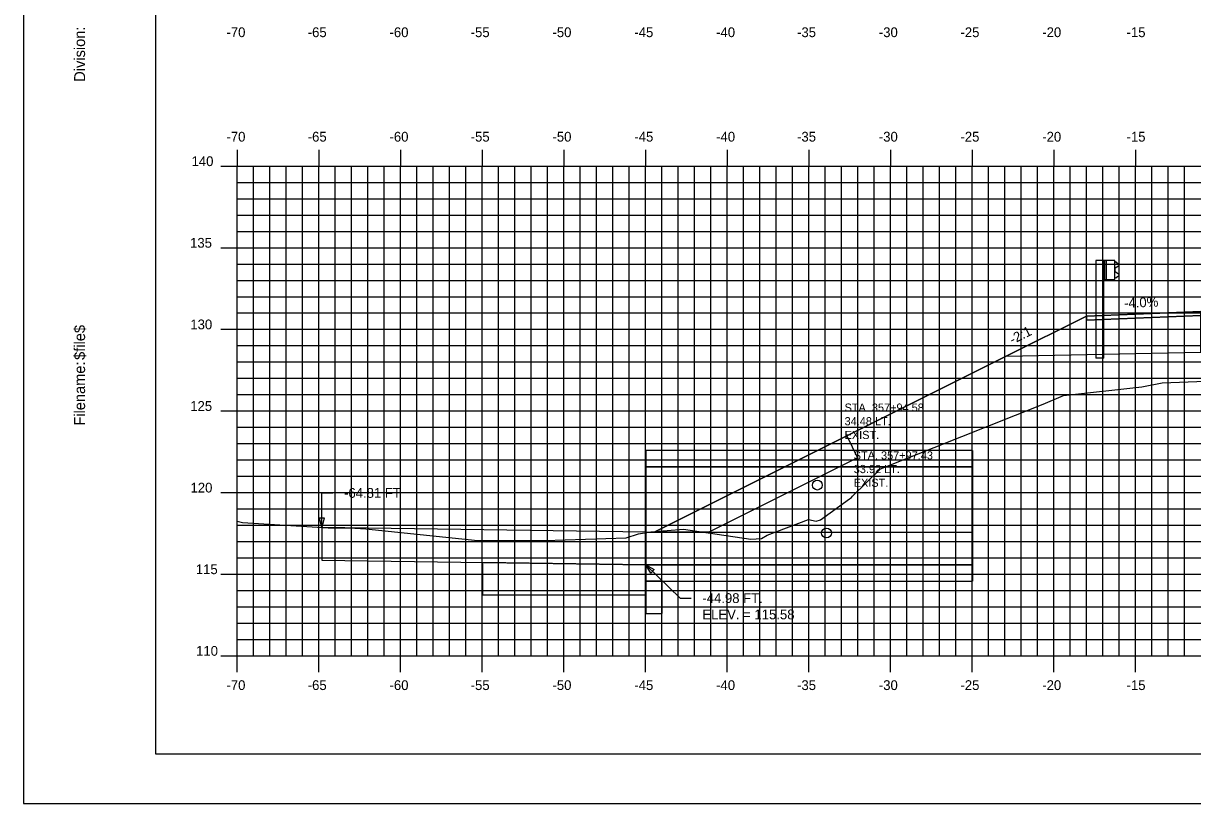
# Model space of a CAD drawing. Extents: x 1146081 to 1146251, y 608981 to 609091.
# Drawn here: x 1146081.1 to 1146152.7, y 608981.3 to 609029.1 of the extents above; entities that cross this region are included whole.
import ezdxf

# ---------------------------------------------------------------- set-up
doc = ezdxf.new("R2010")
doc.units = 0
for name, color, linetype in [('ANNOTATION', 7, 'Continuous'), ('BORDER', 7, 'Continuous'), ('D_Drainage_Culvert', 7, 'Continuous'), ('D_Guardrail_Beam_Lt', 7, 'Continuous'), ('D_Roadway_Edge_Shoulder', 7, 'Continuous'), ('D_Roadway_SlopeLines', 7, 'Continuous'), ('D_Roadway_SubGrade', 7, 'Continuous'), ('D_Text_Monospaced', 7, 'Continuous'), ('D_Text_Standard', 7, 'Continuous'), ('H_V ANNOTATION', 7, 'Continuous'), ('MAJOR', 7, 'Continuous'), ('MINOR', 7, 'Continuous'), ('PATTERNING', 7, 'Continuous'), ('PLOT BOUNDARY', 7, 'Continuous'), ('S_Drainage_Invert', 7, 'Continuous'), ('S_Roadway_Centerline', 7, 'Continuous')]:
    doc.layers.add(name, color=color, linetype=linetype)

msp = doc.modelspace()

# ---------------------------------------------------------------- linework, layer by layer
msp.add_lwpolyline([(1146119.749, 608997.946), (1146139.24, 609007.691), (1146141.24, 609008.691), (1146146.157, 609011.15), (1146146.158, 609011.15), (1146153.158, 609011.43), (1146164.158, 609011.65), (1146175.158, 609011.43), (1146182.158, 609011.15), (1146187.075, 609008.692), (1146189.075, 609007.692), (1146204.079, 609000.19)])
at = {"layer": 'ANNOTATION'}
msp.add_line((1146139.178, 609002.915), (1146139.178, 608994.915), dxfattribs=at)
at = {"layer": 'BORDER'}
msp.add_lwpolyline([(1146089.158, 608984.335), (1146249.158, 608984.335), (1146249.158, 609089.335), (1146089.158, 609089.335)], close=True, dxfattribs=at)
at = {"layer": 'D_Drainage_Culvert'}
for points in [[(1146139.178, 608994.915), (1146139.178, 609002.915), (1146119.178, 609002.915), (1146119.178, 608994.915)], [(1146139.178, 608995.915), (1146139.178, 609001.915), (1146119.178, 609001.915), (1146119.178, 608995.915)], [(1146119.178, 608994.915), (1146119.181, 608992.915), (1146120.181, 608992.916), (1146120.178, 608994.916)]]:
    msp.add_lwpolyline(points, close=True, dxfattribs=at)
at = {"layer": 'D_Guardrail_Beam_Lt'}
for p, q in [((1146146.729, 609014.56), (1146146.729, 609008.56)), ((1146147.2, 609014.56), (1146146.729, 609014.56)), ((1146147.887, 609014.56), (1146147.2, 609014.56)), ((1146147.2, 609014.56), (1146147.2, 609013.394)), ((1146147.262, 609014.56), (1146147.262, 609013.394)), ((1146147.366, 609014.56), (1146147.366, 609013.394)), ((1146147.887, 609013.394), (1146147.887, 609014.56)), ((1146147.887, 609014.477), (1146147.961, 609014.462)), ((1146147.977, 609014.456), (1146148.12, 609014.356)), ((1146147.891, 609014.012), (1146147.891, 609013.942)), ((1146148.12, 609014.213), (1146147.925, 609014.076)), ((1146147.925, 609013.877), (1146148.12, 609013.741)), ((1146148.12, 609013.598), (1146147.977, 609013.498)), ((1146147.2, 609013.394), (1146147.887, 609013.394)), ((1146147.22, 609008.56), (1146147.22, 609013.394)), ((1146147.961, 609013.491), (1146147.887, 609013.477)), ((1146147.22, 609008.56), (1146146.729, 609008.56))]:
    msp.add_line(p, q, dxfattribs=at)
for centre, major_axis, start_param, end_param in [((1146147.953, 609014.422), (0.0417, 0), 0.959931, 1.376053), ((1146148.07, 609014.284), (0.0877, 0), 5.323254, 7.243116), ((1146147.97, 609014.012), (-0.0789, 0), 5.323254, 6.283185), ((1146147.97, 609013.942), (-0.0789, 0), 6.283185, 7.243116), ((1146148.07, 609013.67), (0.0877, 0), 5.323254, 7.243116), ((1146147.953, 609013.532), (0.0417, 0), 4.907132, 5.323254)]:
    msp.add_ellipse(centre, major_axis=major_axis, ratio=0.995501, start_param=start_param, end_param=end_param, dxfattribs=at)
at = {"layer": 'D_Roadway_Edge_Shoulder'}
msp.add_lwpolyline([(1146153.158, 609011.43), (1146146.158, 609011.15), (1146146.158, 609010.9), (1146153.158, 609011.18)], close=True, dxfattribs=at)
at = {"layer": 'D_Roadway_SlopeLines'}
for points in [[(1146141.24, 609008.691), (1146139.24, 609007.691)], [(1146139.24, 609007.691), (1146119.688, 608997.915)]]:
    msp.add_lwpolyline(points, dxfattribs=at)
at = {"layer": 'D_Roadway_SubGrade'}
msp.add_lwpolyline([(1146153.158, 609011.013), (1146153.158, 609011.18), (1146146.158, 609010.9), (1146146.158, 609011.15), (1146146.157, 609011.15), (1146141.24, 609008.691), (1146153.158, 609008.93)], close=True, dxfattribs=at)
at = {"layer": 'D_Text_Standard'}
for points in [[(1146099.348, 608998.2), (1146099.34, 609000.312), (1146100.02, 609000.312)], [(1146119.178, 608995.915), (1146121.28, 608993.866), (1146121.96, 608993.866)]]:
    msp.add_lwpolyline(points, dxfattribs=at)
for points in [[(1146099.348, 608998.2), (1146099.2, 608998.782), (1146099.492, 608998.783)], [(1146119.178, 608995.915), (1146119.697, 608995.613), (1146119.493, 608995.405)]]:
    msp.add_lwpolyline(points, close=True, dxfattribs=at)
at = {"layer": 'MAJOR'}
for p, q in [((1146094.158, 609021.337), (1146094.158, 609020.335)), ((1146099.158, 609021.337), (1146099.158, 609020.335)), ((1146104.158, 609021.337), (1146104.158, 609020.335)), ((1146109.158, 609021.337), (1146109.158, 609020.335)), ((1146114.158, 609021.337), (1146114.158, 609020.335)), ((1146119.158, 609021.337), (1146119.158, 609020.335)), ((1146124.158, 609021.337), (1146124.158, 609020.335)), ((1146129.158, 609021.337), (1146129.158, 609020.335)), ((1146134.158, 609021.337), (1146134.158, 609020.335)), ((1146139.158, 609021.337), (1146139.158, 609020.335)), ((1146144.158, 609021.337), (1146144.158, 609020.335)), ((1146149.158, 609021.337), (1146149.158, 609020.335)), ((1146093.156, 609020.335), (1146094.158, 609020.335)), ((1146094.158, 609020.335), (1146234.158, 609020.335)), ((1146094.158, 608990.335), (1146094.158, 609020.335)), ((1146094.158, 608990.335), (1146094.158, 609020.335)), ((1146094.158, 609020.335), (1146234.158, 609020.335)), ((1146099.158, 608990.335), (1146099.158, 609020.335)), ((1146104.158, 608990.335), (1146104.158, 609020.335)), ((1146109.158, 608990.335), (1146109.158, 609020.335)), ((1146114.158, 608990.335), (1146114.158, 609020.335)), ((1146119.158, 608990.335), (1146119.158, 609020.335)), ((1146124.158, 608990.335), (1146124.158, 609020.335)), ((1146129.158, 608990.335), (1146129.158, 609020.335)), ((1146134.158, 608990.335), (1146134.158, 609020.335)), ((1146139.158, 608990.335), (1146139.158, 609020.335)), ((1146144.158, 608990.335), (1146144.158, 609020.335)), ((1146149.158, 608990.335), (1146149.158, 609020.335)), ((1146093.156, 609015.335), (1146094.158, 609015.335)), ((1146094.158, 609015.335), (1146234.158, 609015.335)), ((1146093.156, 609010.335), (1146094.158, 609010.335)), ((1146094.158, 609010.335), (1146234.158, 609010.335)), ((1146093.156, 609005.335), (1146094.158, 609005.335)), ((1146094.158, 609005.335), (1146234.158, 609005.335)), ((1146093.156, 609000.335), (1146094.158, 609000.335)), ((1146094.158, 609000.335), (1146234.158, 609000.335)), ((1146093.156, 608995.335), (1146094.158, 608995.335)), ((1146094.158, 608995.335), (1146234.158, 608995.335)), ((1146093.156, 608990.335), (1146094.158, 608990.335)), ((1146094.158, 608990.335), (1146234.158, 608990.335)), ((1146094.158, 608990.335), (1146234.158, 608990.335)), ((1146094.158, 608989.333), (1146094.158, 608990.335)), ((1146099.158, 608989.333), (1146099.158, 608990.335)), ((1146104.158, 608989.333), (1146104.158, 608990.335)), ((1146109.158, 608989.333), (1146109.158, 608990.335)), ((1146114.158, 608989.333), (1146114.158, 608990.335)), ((1146119.158, 608989.333), (1146119.158, 608990.335)), ((1146124.158, 608989.333), (1146124.158, 608990.335)), ((1146129.158, 608989.333), (1146129.158, 608990.335)), ((1146134.158, 608989.333), (1146134.158, 608990.335)), ((1146139.158, 608989.333), (1146139.158, 608990.335)), ((1146144.158, 608989.333), (1146144.158, 608990.335)), ((1146149.158, 608989.333), (1146149.158, 608990.335))]:
    msp.add_line(p, q, dxfattribs=at)
at = {"layer": 'MINOR'}
for p, q in [((1146095.158, 608990.335), (1146095.158, 609020.335)), ((1146096.158, 608990.335), (1146096.158, 609020.335)), ((1146097.158, 608990.335), (1146097.158, 609020.335)), ((1146098.158, 608990.335), (1146098.158, 609020.335)), ((1146100.158, 608990.335), (1146100.158, 609020.335)), ((1146101.158, 608990.335), (1146101.158, 609020.335)), ((1146102.158, 608990.335), (1146102.158, 609020.335)), ((1146103.158, 608990.335), (1146103.158, 609020.335)), ((1146105.158, 608990.335), (1146105.158, 609020.335)), ((1146106.158, 608990.335), (1146106.158, 609020.335)), ((1146107.158, 608990.335), (1146107.158, 609020.335)), ((1146108.158, 608990.335), (1146108.158, 609020.335)), ((1146110.158, 608990.335), (1146110.158, 609020.335)), ((1146111.158, 608990.335), (1146111.158, 609020.335)), ((1146112.158, 608990.335), (1146112.158, 609020.335)), ((1146113.158, 608990.335), (1146113.158, 609020.335)), ((1146115.158, 608990.335), (1146115.158, 609020.335)), ((1146116.158, 608990.335), (1146116.158, 609020.335)), ((1146117.158, 608990.335), (1146117.158, 609020.335)), ((1146118.158, 608990.335), (1146118.158, 609020.335)), ((1146120.158, 608990.335), (1146120.158, 609020.335)), ((1146121.158, 608990.335), (1146121.158, 609020.335)), ((1146122.158, 608990.335), (1146122.158, 609020.335)), ((1146123.158, 608990.335), (1146123.158, 609020.335)), ((1146125.158, 608990.335), (1146125.158, 609020.335)), ((1146126.158, 608990.335), (1146126.158, 609020.335)), ((1146127.158, 608990.335), (1146127.158, 609020.335)), ((1146128.158, 608990.335), (1146128.158, 609020.335)), ((1146130.158, 608990.335), (1146130.158, 609020.335)), ((1146131.158, 608990.335), (1146131.158, 609020.335)), ((1146132.158, 608990.335), (1146132.158, 609020.335)), ((1146133.158, 608990.335), (1146133.158, 609020.335)), ((1146135.158, 608990.335), (1146135.158, 609020.335)), ((1146136.158, 608990.335), (1146136.158, 609020.335)), ((1146137.158, 608990.335), (1146137.158, 609020.335)), ((1146138.158, 608990.335), (1146138.158, 609020.335)), ((1146140.158, 608990.335), (1146140.158, 609020.335)), ((1146141.158, 608990.335), (1146141.158, 609020.335)), ((1146142.158, 608990.335), (1146142.158, 609020.335)), ((1146143.158, 608990.335), (1146143.158, 609020.335)), ((1146145.158, 608990.335), (1146145.158, 609020.335)), ((1146146.158, 608990.335), (1146146.158, 609020.335)), ((1146147.158, 608990.335), (1146147.158, 609020.335)), ((1146148.158, 608990.335), (1146148.158, 609020.335)), ((1146150.158, 608990.335), (1146150.158, 609020.335)), ((1146151.158, 608990.335), (1146151.158, 609020.335)), ((1146152.158, 608990.335), (1146152.158, 609020.335)), ((1146094.158, 609019.335), (1146234.158, 609019.335)), ((1146094.158, 609019.335), (1146095.16, 609019.335)), ((1146094.158, 609018.335), (1146234.158, 609018.335)), ((1146094.158, 609018.335), (1146095.16, 609018.335)), ((1146094.158, 609017.335), (1146234.158, 609017.335)), ((1146094.158, 609017.335), (1146095.16, 609017.335)), ((1146094.158, 609016.335), (1146234.158, 609016.335)), ((1146094.158, 609016.335), (1146095.16, 609016.335)), ((1146094.158, 609014.335), (1146234.158, 609014.335)), ((1146094.158, 609014.335), (1146095.16, 609014.335)), ((1146094.158, 609013.335), (1146234.158, 609013.335)), ((1146094.158, 609013.335), (1146095.16, 609013.335)), ((1146094.158, 609012.335), (1146234.158, 609012.335)), ((1146094.158, 609012.335), (1146095.16, 609012.335)), ((1146094.158, 609011.335), (1146234.158, 609011.335)), ((1146094.158, 609011.335), (1146095.16, 609011.335)), ((1146094.158, 609009.335), (1146234.158, 609009.335)), ((1146094.158, 609009.335), (1146095.16, 609009.335)), ((1146094.158, 609008.335), (1146234.158, 609008.335)), ((1146094.158, 609008.335), (1146095.16, 609008.335)), ((1146094.158, 609007.335), (1146234.158, 609007.335)), ((1146094.158, 609007.335), (1146095.16, 609007.335)), ((1146094.158, 609006.335), (1146234.158, 609006.335)), ((1146094.158, 609006.335), (1146095.16, 609006.335)), ((1146094.158, 609004.335), (1146234.158, 609004.335)), ((1146094.158, 609004.335), (1146095.16, 609004.335)), ((1146094.158, 609003.335), (1146234.158, 609003.335)), ((1146094.158, 609003.335), (1146095.16, 609003.335)), ((1146094.158, 609002.335), (1146234.158, 609002.335)), ((1146094.158, 609002.335), (1146095.16, 609002.335)), ((1146094.158, 609001.335), (1146234.158, 609001.335)), ((1146094.158, 609001.335), (1146095.16, 609001.335)), ((1146094.158, 608999.335), (1146234.158, 608999.335)), ((1146094.158, 608999.335), (1146095.16, 608999.335)), ((1146094.158, 608998.335), (1146234.158, 608998.335)), ((1146094.158, 608998.335), (1146095.16, 608998.335)), ((1146094.158, 608997.335), (1146234.158, 608997.335)), ((1146094.158, 608997.335), (1146095.16, 608997.335)), ((1146094.158, 608996.335), (1146234.158, 608996.335)), ((1146094.158, 608996.335), (1146095.16, 608996.335)), ((1146094.158, 608994.335), (1146234.158, 608994.335)), ((1146094.158, 608994.335), (1146095.16, 608994.335)), ((1146094.158, 608993.335), (1146234.158, 608993.335)), ((1146094.158, 608993.335), (1146095.16, 608993.335)), ((1146094.158, 608992.335), (1146234.158, 608992.335)), ((1146094.158, 608992.335), (1146095.16, 608992.335)), ((1146094.158, 608991.335), (1146234.158, 608991.335)), ((1146094.158, 608991.335), (1146095.16, 608991.335))]:
    msp.add_line(p, q, dxfattribs=at)
at = {"layer": 'PATTERNING'}
for p, q in [((1146139.178, 609001.915), (1146139.178, 609002.915)), ((1146119.178, 609001.915), (1146139.178, 609001.915)), ((1146119.178, 608995.915), (1146119.178, 608997.915)), ((1146139.178, 608995.915), (1146119.178, 608995.915)), ((1146119.178, 608995.915), (1146119.178, 608994.915))]:
    msp.add_line(p, q, dxfattribs=at)
for points in [[(1146119.688, 608997.915), (1146129.688, 609002.915), (1146131.477, 609003.81), (1146132.147, 609002.468), (1146123.042, 608997.915)], [(1146119.178, 608995.915), (1146119.178, 608997.915), (1146139.178, 608997.915), (1146139.178, 608995.915)], [(1146119.178, 608995.915), (1146109.179, 608996.059), (1146109.179, 608994.059), (1146119.179, 608994.059)]]:
    msp.add_lwpolyline(points, close=True, dxfattribs=at)
for points in [[(1146139.178, 609002.915), (1146119.178, 609002.915), (1146119.178, 609001.915)], [(1146119.178, 608997.915), (1146099.348, 608998.2), (1146099.348, 608996.2), (1146119.178, 608995.915)], [(1146119.178, 608997.915), (1146099.348, 608998.2), (1146099.348, 608996.2), (1146119.178, 608995.915)], [(1146119.178, 608994.915), (1146139.178, 608994.915), (1146139.178, 608995.915)]]:
    msp.add_lwpolyline(points, dxfattribs=at)
at = {"layer": 'PLOT BOUNDARY'}
msp.add_lwpolyline([(1146081.065, 608981.276), (1146251.065, 608981.276), (1146251.065, 609091.276), (1146081.065, 609091.276)], close=True, dxfattribs=at)
at = {"layer": 'S_Drainage_Invert'}
for centre in [(1146129.681, 609000.79), (1146130.241, 608997.862)]:
    msp.add_circle(centre, 0.3, dxfattribs=at)
at = {"layer": 'S_Roadway_Centerline'}
msp.add_lwpolyline([(1146094.158, 608998.573), (1146094.475, 608998.506), (1146099.727, 608998.176), (1146100.855, 608998.172), (1146101.03, 608998.172), (1146102.033, 608998.119), (1146108.892, 608997.397), (1146112.993, 608997.403), (1146117.978, 608997.561), (1146118.726, 608997.813), (1146119.493, 608997.926), (1146121.478, 608998.081), (1146125.609, 608997.484), (1146126.267, 608997.517), (1146126.607, 608997.722), (1146129.147, 608998.69), (1146129.609, 608998.572), (1146129.867, 608998.658), (1146131.658, 608999.946), (1146131.77, 609000.037), (1146131.842, 609000.108), (1146133.543, 609001.779), (1146143.511, 609005.755), (1146144.747, 609006.275), (1146149.547, 609006.818), (1146150.798, 609007.066), (1146159.846, 609007.401)], dxfattribs=at)

# ---------------------------------------------------------------- texts
at = {"layer": 'ANNOTATION'}
for s, rotation, p in [('-4.0%', 2.29061, (1146148.474, 609011.643)), ('-2:1', 26.56505, (1146141.628, 609009.403))]:
    msp.add_text(s, height=0.6, rotation=rotation, dxfattribs=at).set_placement(p)
at = {"layer": 'BORDER'}
for s, p in [('Division:', (1146084.843, 609025.501)), ('$file$', (1146084.843, 609008.461)), ('Filename:', (1146084.843, 609004.433))]:
    msp.add_text(s, height=0.6696, rotation=90, dxfattribs=at).set_placement(p)
at = {"layer": 'D_Text_Monospaced'}
for s, height, p in [('STA. 357+94.58', 0.49998, (1146131.348, 609005.288)), ('34.48 LT.', 0.5, (1146131.348, 609004.454)), ('EXIST. ', 0.5, (1146131.348, 609003.614)), ('STA. 357+97.43', 0.49998, (1146131.908, 609002.36)), ('33.92 LT.', 0.5, (1146131.908, 609001.526)), ('EXIST. ', 0.5, (1146131.908, 609000.686))]:
    msp.add_text(s, height=height, dxfattribs=at).set_placement(p)
at = {"layer": 'D_Text_Standard'}
for s, p in [('-64.81 FT', (1146100.7, 609000.012)), ('-44.98 FT.', (1146122.64, 608993.566)), ('ELEV. = 115.58', (1146122.64, 608992.566))]:
    msp.add_text(s, height=0.6, dxfattribs=at).set_placement(p)
at = {"layer": 'H_V ANNOTATION'}
for s, p in [('-70', (1146093.5, 609028.235)), ('-65', (1146098.476, 609028.235)), ('-60', (1146103.484, 609028.235)), ('-55', (1146108.454, 609028.235)), ('-50', (1146113.462, 609028.235)), ('-45', (1146118.476, 609028.235)), ('-40', (1146123.484, 609028.235)), ('-35', (1146128.438, 609028.235)), ('-30', (1146133.446, 609028.235)), ('-25', (1146138.444, 609028.235)), ('-20', (1146143.452, 609028.235)), ('-15', (1146148.615, 609028.235)), ('-70', (1146093.5, 609021.835)), ('-65', (1146098.476, 609021.835)), ('-60', (1146103.484, 609021.835)), ('-55', (1146108.454, 609021.835)), ('-50', (1146113.462, 609021.835)), ('-45', (1146118.476, 609021.835)), ('-40', (1146123.484, 609021.835)), ('-35', (1146128.438, 609021.835)), ('-30', (1146133.446, 609021.835)), ('-25', (1146138.444, 609021.835)), ('-20', (1146143.452, 609021.835)), ('-15', (1146148.615, 609021.835)), ('140', (1146091.363, 609020.335)), ('135', (1146091.272, 609015.335)), ('130', (1146091.288, 609010.335)), ('125', (1146091.283, 609005.335)), ('120', (1146091.299, 609000.335)), ('115', (1146091.625, 608995.335)), ('110', (1146091.641, 608990.335)), ('-70', (1146093.5, 608988.235)), ('-65', (1146098.476, 608988.235)), ('-60', (1146103.484, 608988.235)), ('-55', (1146108.454, 608988.235)), ('-50', (1146113.462, 608988.235)), ('-45', (1146118.476, 608988.235)), ('-40', (1146123.484, 608988.235)), ('-35', (1146128.438, 608988.235)), ('-30', (1146133.446, 608988.235)), ('-25', (1146138.444, 608988.235)), ('-20', (1146143.452, 608988.235)), ('-15', (1146148.615, 608988.235))]:
    msp.add_text(s, height=0.6, dxfattribs=at).set_placement(p)
at = {"layer": 'MAJOR'}
msp.add_text('-', height=0.006, dxfattribs=at).set_placement((1146094.154, 608990.335))

doc.saveas('drawing.dxf')
